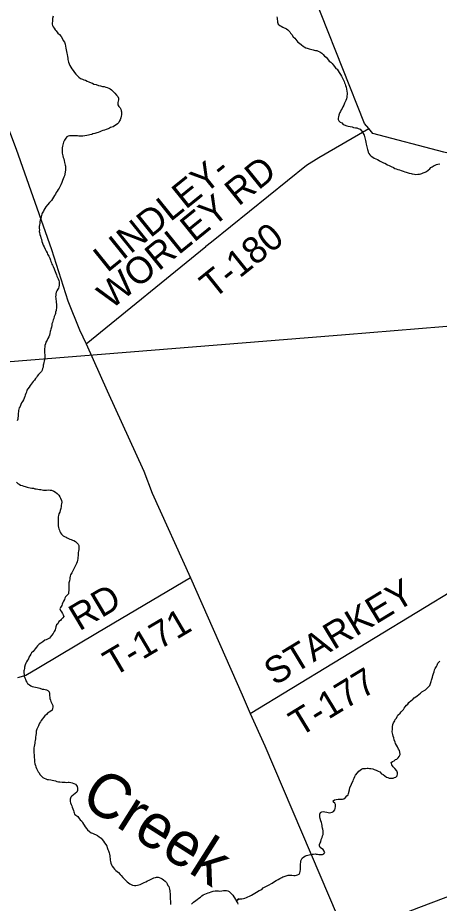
# Model space of a CAD drawing. Extents: x 0 to 1064, y 0 to 440.
# Drawn here: x 336.06 to 350.49, y 49.63 to 79.88 of the extents above; entities that cross this region are included whole.
import ezdxf

# ---------------------------------------------------------------- set-up
doc = ezdxf.new("R2010")
doc.units = 0
for name, color, linetype in [('GM_X_County_Road', 7, 'Continuous'), ('GM_X_Minor_River', 7, 'Continuous'), ('GM_X_Minor_River_Text', 7, 'Continuous'), ('GM_X_Rail_Line', 7, 'Continuous'), ('GM_X_State_Route', 7, 'Continuous'), ('GM_X_Township_Road', 7, 'Continuous'), ('GM_X_Township_Road_Text', 7, 'Continuous')]:
    doc.layers.add(name, color=color, linetype=linetype)

msp = doc.modelspace()

# ---------------------------------------------------------------- linework, layer by layer
at = {"layer": 'GM_X_County_Road'}
for points in [[(332.472, 81.833), (334.396, 78.519), (335.465, 76.831), (336.008, 75.395), (337.22, 71.966), (337.783, 70.207), (338.181, 69.223), (338.401, 68.74), (339.129, 67.136), (340.376, 64.388), (340.662, 63.636), (341.974, 60.741), (343.737, 56.745), (344.022, 56.108), (344.519, 55.001), (346.397, 50.602), (347.286, 48.52)], [(374.507, 71.33), (372.27, 72.9), (368.291, 75.769), (368.159, 75.856), (367.867, 75.885), (362.558, 75.761), (360.734, 75.905), (359.635, 76.08), (358.571, 76.181), (357.992, 76.105), (357.429, 75.907), (356.927, 75.727), (354.046, 75.188), (352.338, 74.965), (351.809, 75.028), (350.645, 75.289), (348.214, 75.929), (348.075, 76.096), (347.933, 76.267), (345.702, 81.875)]]:
    msp.add_lwpolyline(points, dxfattribs=at)
at = {"layer": 'GM_X_Minor_River'}
for points in [[(337.273, 79.934), (337.259, 79.849), (337.252, 79.807), (337.251, 79.752), (337.243, 79.71), (337.248, 79.661), (337.259, 79.618), (337.276, 79.569), (337.306, 79.52), (337.341, 79.47), (337.382, 79.427), (337.436, 79.358), (337.495, 79.302), (337.548, 79.234), (337.601, 79.154), (337.624, 79.105), (337.665, 79.043), (337.688, 78.975), (337.704, 78.914), (337.715, 78.841), (337.72, 78.786), (337.736, 78.731), (337.741, 78.67), (337.752, 78.627), (337.769, 78.554), (337.779, 78.493), (337.784, 78.45), (337.806, 78.365), (337.823, 78.309), (337.846, 78.248), (337.887, 78.186), (337.916, 78.131), (337.957, 78.075), (338.011, 78.013), (338.058, 77.957), (338.117, 77.889), (338.159, 77.851), (338.213, 77.808), (338.279, 77.782), (338.327, 77.762)], [(344.931, 79.914), (344.936, 79.865), (344.941, 79.822), (344.946, 79.773), (344.951, 79.731), (344.979, 79.657), (345.027, 79.613), (345.075, 79.588), (345.129, 79.562), (345.177, 79.537), (345.219, 79.524)], [(345.219, 79.524), (345.261, 79.498), (345.309, 79.461), (345.368, 79.398), (345.398, 79.355), (345.445, 79.305), (345.486, 79.231), (345.54, 79.181), (345.575, 79.138), (345.61, 79.095), (345.646, 79.045), (345.706, 79.007), (345.771, 78.951), (345.825, 78.913), (345.867, 78.882), (345.915, 78.856), (345.969, 78.837), (346.03, 78.817), (346.078, 78.804), (346.126, 78.796), (346.169, 78.783), (346.211, 78.77), (346.253, 78.763), (346.296, 78.756), (346.344, 78.736), (346.398, 78.711), (346.464, 78.673), (346.512, 78.629), (346.559, 78.567), (346.613, 78.529), (346.66, 78.48), (346.719, 78.399), (346.779, 78.361), (346.82, 78.312), (346.856, 78.268), (346.903, 78.218), (346.95, 78.15), (346.992, 78.119), (347.021, 78.07), (347.056, 78.008), (347.103, 77.94), (347.139, 77.884), (347.185, 77.798), (347.208, 77.749), (347.237, 77.7), (347.248, 77.657), (347.266, 77.608), (347.283, 77.565), (347.299, 77.503), (347.316, 77.442), (347.321, 77.375), (347.331, 77.302), (347.33, 77.26), (347.323, 77.217), (347.321, 77.162), (347.308, 77.108), (347.288, 77.048), (347.269, 77.006), (347.243, 76.958), (347.217, 76.897), (347.185, 76.837), (347.166, 76.777), (347.134, 76.729), (347.108, 76.681), (347.089, 76.639), (347.064, 76.591), (347.044, 76.549), (347.037, 76.494), (347.024, 76.452), (347.028, 76.403), (347.046, 76.36), (347.099, 76.317), (347.147, 76.285), (347.195, 76.235), (347.237, 76.216), (347.327, 76.183), (347.37, 76.176), (347.442, 76.162), (347.503, 76.149), (347.551, 76.135), (347.624, 76.121), (347.667, 76.114), (347.715, 76.101), (347.775, 76.069), (347.822, 76.019), (347.87, 75.964), (347.881, 75.921), (347.916, 75.865), (347.927, 75.822), (347.949, 75.731), (347.96, 75.682), (347.971, 75.627), (347.988, 75.566), (347.999, 75.517), (348.01, 75.468), (348.026, 75.382), (348.037, 75.339), (348.054, 75.29), (348.077, 75.247), (348.112, 75.192), (348.16, 75.148)], [(338.327, 77.762), (338.381, 77.743), (338.435, 77.711), (338.502, 77.691), (338.574, 77.653), (338.622, 77.64), (338.67, 77.614), (338.749, 77.594), (338.833, 77.562), (338.9, 77.548), (338.961, 77.534), (339.027, 77.526), (339.082, 77.507), (339.13, 77.494), (339.178, 77.474), (339.226, 77.449), (339.268, 77.417), (339.322, 77.373), (339.387, 77.299), (339.446, 77.237), (339.488, 77.187), (339.511, 77.132), (339.509, 77.077), (339.502, 77.029), (339.495, 76.986), (339.488, 76.944), (339.493, 76.901), (339.522, 76.846), (339.569, 76.796), (339.592, 76.753), (339.609, 76.704), (339.614, 76.661), (339.613, 76.612), (339.612, 76.564), (339.605, 76.515), (339.597, 76.461), (339.571, 76.395), (339.552, 76.352), (339.52, 76.299), (339.483, 76.257), (339.427, 76.216), (339.377, 76.186), (339.328, 76.157), (339.285, 76.146), (339.242, 76.129), (339.199, 76.112), (339.156, 76.088), (339.088, 76.066), (339.039, 76.043), (338.978, 76.026), (338.922, 76.009), (338.873, 75.986), (338.812, 75.963), (338.769, 75.952), (338.701, 75.929), (338.64, 75.912), (338.597, 75.895), (338.536, 75.878), (338.487, 75.867), (338.432, 75.857), (338.358, 75.84), (338.297, 75.835), (338.254, 75.83), (338.206, 75.832), (338.151, 75.839), (338.109, 75.84), (338.066, 75.841), (338.017, 75.848), (337.957, 75.85), (337.914, 75.845), (337.835, 75.841), (337.792, 75.835), (337.742, 75.806), (337.705, 75.765), (337.661, 75.699), (337.628, 75.627), (337.608, 75.542), (337.595, 75.494), (337.587, 75.439), (337.585, 75.36), (337.584, 75.299), (337.589, 75.257), (337.593, 75.202), (337.605, 75.159), (337.615, 75.11), (337.638, 75.055), (337.655, 75), (337.666, 74.933), (337.688, 74.847), (337.699, 74.804), (337.704, 74.755), (337.703, 74.713), (337.696, 74.67), (337.688, 74.61), (337.674, 74.531), (337.661, 74.477), (337.647, 74.434), (337.616, 74.38), (337.596, 74.314), (337.57, 74.248), (337.543, 74.175)], [(348.16, 75.148), (348.208, 75.116), (348.256, 75.085), (348.31, 75.059), (348.37, 75.033), (348.424, 75.002), (348.466, 74.976), (348.508, 74.957), (348.58, 74.925), (348.622, 74.906), (348.719, 74.855), (348.773, 74.829), (348.845, 74.797), (348.923, 74.759), (348.965, 74.733), (349.007, 74.72), (349.068, 74.7), (349.128, 74.681), (349.182, 74.661), (349.255, 74.635), (349.309, 74.616), (349.358, 74.602), (349.418, 74.583), (349.46, 74.575), (349.521, 74.556), (349.563, 74.549), (349.636, 74.535), (349.678, 74.528), (349.751, 74.532), (349.806, 74.537), (349.849, 74.548), (349.892, 74.559), (349.935, 74.576), (349.997, 74.605), (350.046, 74.628), (350.108, 74.675), (350.158, 74.723), (350.201, 74.758), (350.245, 74.788), (350.307, 74.829), (350.35, 74.846), (350.393, 74.863), (350.436, 74.88), (350.509, 74.891)], [(337.543, 74.175), (337.518, 74.121), (337.48, 74.055), (337.448, 74.014), (337.416, 73.96), (337.384, 73.906), (337.359, 73.858), (337.327, 73.804), (337.289, 73.75), (337.251, 73.696), (337.226, 73.636), (337.182, 73.607), (337.151, 73.565), (337.088, 73.487), (337.031, 73.422), (336.987, 73.362), (336.956, 73.308), (336.942, 73.266), (336.904, 73.206), (336.891, 73.164), (336.878, 73.121), (336.865, 73.073), (336.851, 73.025), (336.831, 72.971), (336.818, 72.904), (336.816, 72.855), (336.809, 72.807), (336.802, 72.746), (336.8, 72.685), (336.805, 72.637), (336.803, 72.582), (336.815, 72.539), (336.825, 72.478), (336.842, 72.423), (336.859, 72.356), (336.876, 72.313), (336.892, 72.239), (336.915, 72.184), (336.938, 72.111), (336.967, 72.049), (337.007, 71.969), (337.042, 71.901), (337.071, 71.846), (337.088, 71.797), (337.129, 71.729), (337.158, 71.661), (337.181, 71.6), (337.198, 71.551), (337.215, 71.508), (337.232, 71.465), (337.249, 71.422), (337.273, 71.379), (337.307, 71.305), (337.324, 71.262), (337.348, 71.213), (337.364, 71.158), (337.393, 71.096), (337.404, 71.054), (337.428, 71.01), (337.451, 70.961), (337.474, 70.906), (337.479, 70.857), (337.483, 70.802), (337.488, 70.748), (337.474, 70.687), (337.455, 70.645), (337.436, 70.603), (337.404, 70.549), (337.385, 70.501), (337.371, 70.446), (337.364, 70.398), (337.362, 70.349), (337.367, 70.294), (337.372, 70.252), (337.377, 70.209), (337.382, 70.16), (337.386, 70.081), (337.391, 70.02), (337.389, 69.96), (337.382, 69.917), (337.375, 69.875), (337.361, 69.82), (337.36, 69.778), (337.341, 69.736), (337.315, 69.669), (337.295, 69.609), (337.282, 69.561), (337.269, 69.519), (337.255, 69.47), (337.236, 69.422), (337.228, 69.368), (337.215, 69.307), (337.195, 69.241), (337.181, 69.198), (337.174, 69.156), (337.167, 69.089), (337.147, 69.035), (337.133, 68.981), (337.096, 68.927), (337.07, 68.861), (337.031, 68.795)], [(337.031, 68.795), (337.012, 68.74), (336.992, 68.686), (336.991, 68.631), (336.983, 68.577), (336.976, 68.528), (336.981, 68.474), (336.985, 68.419), (336.99, 68.376), (336.989, 68.303), (336.987, 68.242), (336.986, 68.2), (336.972, 68.145), (336.959, 68.097), (336.946, 68.049), (336.939, 68.006), (336.931, 67.946), (336.917, 67.891), (336.904, 67.843), (336.884, 67.789), (336.835, 67.748), (336.772, 67.688), (336.734, 67.634), (336.709, 67.592), (336.678, 67.551), (336.64, 67.503), (336.596, 67.449), (336.558, 67.402), (336.521, 67.36), (336.489, 67.318), (336.451, 67.258), (336.413, 67.204), (336.382, 67.156), (336.362, 67.09), (336.342, 67.042), (336.323, 66.988), (336.309, 66.939), (336.283, 66.879), (336.258, 66.825), (336.226, 66.771), (336.194, 66.723), (336.169, 66.669), (336.148, 66.597), (336.117, 66.555), (336.104, 66.513), (336.096, 66.464), (336.089, 66.416), (336.082, 66.367), (336.081, 66.319), (336.079, 66.27), (336.072, 66.215), (336.065, 66.167), (336.051, 66.106)], [(336.023, 64.016), (336.064, 63.972), (336.112, 63.94), (336.16, 63.915), (336.221, 63.895), (336.269, 63.876), (336.323, 63.862)], [(336.323, 63.862), (336.384, 63.843), (336.438, 63.829), (336.487, 63.822), (336.553, 63.808), (336.602, 63.807), (336.65, 63.788), (336.693, 63.781), (336.808, 63.766), (336.85, 63.758), (336.948, 63.744), (337.002, 63.743), (337.051, 63.741), (337.118, 63.746), (337.179, 63.738), (337.221, 63.737), (337.3, 63.705), (337.354, 63.673), (337.413, 63.629), (337.467, 63.573), (337.502, 63.518), (337.525, 63.469), (337.56, 63.389), (337.57, 63.328), (337.563, 63.279), (337.555, 63.225), (337.548, 63.182), (337.534, 63.11), (337.515, 63.049), (337.501, 62.989), (337.475, 62.929), (337.461, 62.874), (337.454, 62.826), (337.453, 62.777), (337.452, 62.723), (337.45, 62.662), (337.449, 62.613), (337.454, 62.564), (337.453, 62.522), (337.463, 62.461), (337.474, 62.418), (337.491, 62.369), (337.509, 62.326), (337.532, 62.283), (337.567, 62.239), (337.621, 62.183), (337.663, 62.158), (337.717, 62.132), (337.759, 62.113), (337.807, 62.094), (337.849, 62.068), (337.891, 62.055), (337.94, 62.036), (337.988, 62.016), (338.036, 61.985), (338.089, 61.941), (338.137, 61.891), (338.154, 61.848), (338.159, 61.793), (338.152, 61.751), (338.151, 61.709), (338.143, 61.66), (338.136, 61.612), (338.128, 61.557), (338.127, 61.496), (338.12, 61.454), (338.118, 61.399), (338.105, 61.345), (338.098, 61.296), (338.078, 61.236), (338.046, 61.17), (338.014, 61.116), (338.001, 61.074), (337.975, 61.026), (337.937, 60.966), (337.911, 60.912), (337.873, 60.846), (337.86, 60.803), (337.846, 60.749), (337.845, 60.707), (337.832, 60.646), (337.818, 60.573), (337.817, 60.525), (337.815, 60.464), (337.814, 60.415), (337.813, 60.367), (337.811, 60.318), (337.804, 60.258), (337.802, 60.203), (337.752, 60.149), (337.702, 60.096), (337.677, 60.048), (337.664, 60.006), (337.632, 59.946), (337.606, 59.898), (337.586, 59.843), (337.573, 59.801), (337.523, 59.735), (337.509, 59.681), (337.532, 59.632), (337.568, 59.582)], [(337.568, 59.582), (337.597, 59.527), (337.62, 59.484), (337.637, 59.429), (337.605, 59.375), (337.549, 59.327), (337.524, 59.285), (337.474, 59.25), (337.436, 59.178), (337.386, 59.137), (337.372, 59.07), (337.359, 59.01), (337.345, 58.967), (337.307, 58.908), (337.281, 58.841), (337.225, 58.776), (337.181, 58.728), (337.149, 58.68), (337.106, 58.657), (337.039, 58.628), (336.995, 58.611), (336.927, 58.564), (336.853, 58.517), (336.803, 58.476), (336.747, 58.423), (336.71, 58.375), (336.659, 58.321), (336.622, 58.274), (336.59, 58.232), (336.54, 58.184), (336.509, 58.142), (336.477, 58.082), (336.445, 58.035), (336.432, 57.98), (336.394, 57.932), (336.368, 57.878), (336.343, 57.83), (336.323, 57.77), (336.297, 57.698), (336.296, 57.649), (336.282, 57.607), (336.275, 57.564), (336.274, 57.516), (336.284, 57.437), (336.289, 57.388), (336.306, 57.333), (336.329, 57.283), (336.346, 57.222), (336.375, 57.179), (336.405, 57.136), (336.464, 57.086), (336.512, 57.054), (336.56, 57.035), (336.615, 57.027), (336.669, 57.014), (336.73, 57), (336.772, 56.987), (336.821, 56.974), (336.899, 56.947), (336.96, 56.94), (337.002, 56.933), (337.05, 56.919), (337.099, 56.894), (337.14, 56.85), (337.151, 56.789), (337.155, 56.716), (337.16, 56.668), (337.165, 56.625), (337.188, 56.57), (337.199, 56.521), (337.222, 56.471), (337.239, 56.428), (337.262, 56.379), (337.267, 56.324), (337.26, 56.276), (337.246, 56.228), (337.203, 56.186), (337.141, 56.157), (337.098, 56.128), (337.048, 56.08), (336.992, 56.033), (336.948, 55.979), (336.91, 55.926), (336.866, 55.872), (336.841, 55.83), (336.815, 55.782), (336.789, 55.728), (336.776, 55.686), (336.757, 55.638), (336.718, 55.572), (336.699, 55.505), (336.691, 55.438), (336.683, 55.36), (336.675, 55.311), (336.668, 55.244), (336.66, 55.184), (336.653, 55.141), (336.646, 55.093), (336.638, 55.045), (336.625, 54.984), (336.617, 54.936)], [(349.843, 56.8), (349.887, 56.847), (350.017, 56.923), (350.054, 56.965), (350.161, 57.072), (350.181, 57.138), (350.213, 57.204), (350.22, 57.247), (350.253, 57.349), (350.26, 57.41), (350.287, 57.482), (350.306, 57.536), (350.326, 57.597), (350.34, 57.651), (350.39, 57.717), (350.409, 57.759), (350.441, 57.825), (350.51, 57.896)], [(346.936, 52.997), (346.913, 53.052), (346.871, 53.077), (346.86, 53.126), (346.903, 53.162), (346.959, 53.178), (347.026, 53.183), (347.074, 53.182), (347.123, 53.181), (347.172, 53.185), (347.221, 53.196), (347.277, 53.238), (347.321, 53.297), (347.364, 53.327), (347.378, 53.381), (347.411, 53.502), (347.425, 53.587), (347.476, 53.665), (347.496, 53.725), (347.535, 53.815), (347.548, 53.857), (347.573, 53.899), (347.593, 53.954), (347.618, 54.008), (347.687, 54.079), (347.737, 54.139), (347.781, 54.174), (347.824, 54.209), (347.867, 54.227), (347.922, 54.231), (347.965, 54.236), (348.014, 54.241), (348.057, 54.24), (348.099, 54.233), (348.148, 54.232), (348.208, 54.218), (348.262, 54.199), (348.323, 54.173), (348.395, 54.141), (348.449, 54.115), (348.514, 54.053), (348.562, 54.021), (348.622, 53.983), (348.682, 53.933), (348.724, 53.92), (348.773, 53.907), (348.827, 53.9), (348.906, 53.898), (348.956, 53.921), (348.999, 53.938), (349.042, 53.986), (349.056, 54.046), (349.057, 54.089), (349.028, 54.15), (348.963, 54.237), (348.91, 54.287), (348.863, 54.355), (348.846, 54.398), (348.841, 54.44), (348.89, 54.476), (348.946, 54.499), (348.989, 54.534), (349.032, 54.551), (349.076, 54.599), (349.108, 54.647), (349.152, 54.713), (349.136, 54.786), (349.125, 54.847), (349.096, 54.89), (349.055, 54.976), (349.02, 55.026), (348.991, 55.081), (348.974, 55.136), (348.939, 55.216), (348.929, 55.277), (348.906, 55.339), (348.895, 55.388), (348.879, 55.479), (348.881, 55.57), (348.883, 55.655), (348.897, 55.734), (348.917, 55.794), (348.962, 55.86), (348.981, 55.902), (349.019, 55.95), (349.05, 56.01), (349.07, 56.052), (349.151, 56.117), (349.182, 56.171), (349.257, 56.248), (349.289, 56.296), (349.32, 56.338), (349.364, 56.392), (349.408, 56.433), (349.446, 56.481), (349.521, 56.552), (349.564, 56.575), (349.627, 56.647), (349.682, 56.676), (349.726, 56.717), (349.843, 56.8)], [(336.617, 54.936), (336.616, 54.881), (336.615, 54.826), (336.619, 54.771), (336.624, 54.704), (336.629, 54.656), (336.633, 54.601), (336.638, 54.546), (336.643, 54.503), (336.642, 54.455), (336.652, 54.388), (336.669, 54.338), (336.686, 54.289), (336.709, 54.234), (336.738, 54.167), (336.761, 54.123), (336.797, 54.08), (336.82, 54.031), (336.879, 53.969), (336.927, 53.919), (336.969, 53.9), (337.023, 53.874), (337.071, 53.855), (337.12, 53.853), (337.193, 53.846), (337.247, 53.838), (337.302, 53.825), (337.362, 53.811), (337.404, 53.792), (337.459, 53.772), (337.507, 53.771), (337.586, 53.763), (337.647, 53.762), (337.69, 53.761), (337.744, 53.759), (337.787, 53.764), (337.83, 53.763), (337.884, 53.75), (337.927, 53.743), (337.987, 53.723), (338.041, 53.697), (338.077, 53.654), (338.1, 53.611), (338.105, 53.562), (338.11, 53.519), (338.115, 53.477), (338.089, 53.423), (338.033, 53.375), (337.977, 53.328), (337.921, 53.287), (337.878, 53.257), (337.858, 53.185), (337.856, 53.106), (337.867, 53.063), (337.89, 53.002), (337.913, 52.959), (337.93, 52.91), (337.947, 52.854), (337.976, 52.799), (337.987, 52.756), (337.998, 52.713), (338.003, 52.671), (338.057, 52.633), (338.123, 52.589), (338.164, 52.527), (338.206, 52.483), (338.253, 52.428), (338.276, 52.384), (338.311, 52.335), (338.335, 52.292), (338.37, 52.242), (338.417, 52.186), (338.452, 52.131), (338.518, 52.075), (338.578, 52.037), (338.62, 52.024), (338.674, 51.998), (338.747, 51.966), (338.795, 51.94), (338.854, 51.896), (338.914, 51.846), (338.949, 51.803), (338.997, 51.753), (339.032, 51.691), (339.079, 51.635), (339.108, 51.574), (339.125, 51.531), (339.148, 51.47), (339.171, 51.42), (339.194, 51.347), (339.205, 51.304), (339.216, 51.249), (339.22, 51.2), (339.225, 51.158), (339.23, 51.097), (339.241, 51.054), (339.252, 50.999), (339.275, 50.938), (339.298, 50.894), (339.345, 50.833), (339.375, 50.789)], [(343.627, 49.775), (343.542, 49.71), (343.659, 49.78), (343.732, 49.778), (343.793, 49.789), (343.836, 49.806), (343.892, 49.823), (343.941, 49.846), (343.99, 49.869), (344.058, 49.904), (344.114, 49.939), (344.175, 49.974), (344.231, 50.009), (344.324, 50.068), (344.41, 50.102), (344.46, 50.15), (344.577, 50.208), (344.639, 50.249), (344.768, 50.319), (344.812, 50.348), (344.905, 50.407), (344.972, 50.435), (345.034, 50.47), (345.096, 50.505), (345.139, 50.535), (345.182, 50.546), (345.25, 50.569), (345.311, 50.585), (345.36, 50.59), (345.439, 50.588), (345.506, 50.581), (345.554, 50.58), (345.597, 50.585), (345.64, 50.596), (345.695, 50.625), (345.715, 50.673), (345.728, 50.715), (345.742, 50.776), (345.743, 50.836), (345.739, 50.897), (345.741, 50.976), (345.748, 51.025), (345.755, 51.079), (345.775, 51.121), (345.8, 51.163), (345.856, 51.211), (345.906, 51.246), (345.949, 51.263), (345.992, 51.274), (346.035, 51.285), (346.083, 51.296), (346.139, 51.307), (346.181, 51.306), (346.236, 51.311), (346.279, 51.31), (346.321, 51.303), (346.364, 51.296), (346.43, 51.288), (346.485, 51.293), (346.541, 51.316), (346.572, 51.358), (346.549, 51.413), (346.508, 51.462), (346.46, 51.494), (346.412, 51.538), (346.389, 51.587), (346.39, 51.636), (346.41, 51.69), (346.429, 51.732), (346.443, 51.811), (346.482, 51.877), (346.495, 51.931), (346.508, 51.979), (346.51, 52.052), (346.511, 52.101), (346.507, 52.156), (346.496, 52.198), (346.479, 52.248), (346.474, 52.29), (346.463, 52.339), (346.452, 52.388), (346.435, 52.449), (346.407, 52.529), (346.396, 52.578), (346.397, 52.62), (346.404, 52.669), (346.424, 52.723), (346.467, 52.752), (346.528, 52.763), (346.571, 52.756), (346.637, 52.742), (346.679, 52.729), (346.734, 52.722), (346.777, 52.727), (346.82, 52.738), (346.869, 52.761), (346.907, 52.821), (346.92, 52.869), (346.94, 52.93), (346.936, 52.997)], [(339.375, 50.789), (339.422, 50.746), (339.464, 50.714), (339.512, 50.677), (339.571, 50.614), (339.606, 50.571), (339.66, 50.503), (339.707, 50.459), (339.749, 50.421), (339.808, 50.359), (339.856, 50.322), (339.898, 50.296), (339.946, 50.271), (339.994, 50.245), (340.055, 50.238), (340.109, 50.23), (340.164, 50.241), (340.207, 50.252), (340.25, 50.27), (340.299, 50.287), (340.349, 50.31), (340.392, 50.339), (340.447, 50.362), (340.509, 50.391), (340.564, 50.414), (340.626, 50.449), (340.676, 50.478), (340.725, 50.495), (340.774, 50.512), (340.817, 50.517), (340.865, 50.516), (340.908, 50.503), (340.962, 50.483), (341.004, 50.464), (341.052, 50.433), (341.105, 50.383), (341.153, 50.339), (341.182, 50.296), (341.205, 50.24), (341.229, 50.197), (341.246, 50.154), (341.257, 50.112), (341.268, 50.057), (341.273, 50.008), (341.278, 49.965), (341.276, 49.91), (341.281, 49.862), (341.28, 49.819), (341.285, 49.758), (341.289, 49.709), (341.288, 49.637), (341.292, 49.582)], [(342.005, 49.595), (342.073, 49.66), (342.154, 49.719), (342.198, 49.754), (342.266, 49.801), (342.315, 49.831), (342.365, 49.878), (342.409, 49.914), (342.47, 49.942), (342.519, 49.959), (342.581, 49.988), (342.624, 50), (342.679, 50.023), (342.753, 50.045), (342.814, 50.05), (342.881, 50.048), (342.935, 50.047), (342.978, 50.046), (343.045, 50.05), (343.106, 50.061), (343.161, 50.066), (343.204, 50.065), (343.258, 50.057), (343.3, 50.032), (343.348, 49.988), (343.377, 49.945), (343.419, 49.907), (343.454, 49.852), (343.483, 49.809), (343.512, 49.753), (343.542, 49.71), (343.583, 49.648), (343.6, 49.593)]]:
    msp.add_lwpolyline(points, dxfattribs=at)
at = {"layer": 'GM_X_Rail_Line'}
msp.add_lwpolyline([(294.878, 64.688), (295.462, 64.818), (295.993, 64.914), (296.456, 64.984), (296.949, 65.05), (297.395, 65.101), (298.637, 65.203), (300.032, 65.313), (301.845, 65.455), (308.155, 65.944), (313.085, 66.333), (315.754, 66.545), (319.164, 66.817), (322.97, 67.113), (325.111, 67.285), (328.704, 67.57), (338.651, 68.362), (347.277, 69.057), (351.435, 69.397), (364.628, 70.454), (374.547, 71.26), (377.035, 71.469), (383.382, 71.976), (390.331, 72.542)], dxfattribs=at)
at = {"layer": 'GM_X_State_Route'}
msp.add_lwpolyline([(345.62, 47.878), (346.678, 48.282), (347.286, 48.52), (347.579, 48.634), (348.671, 49.054), (349.782, 49.485), (350.72, 49.841), (351.738, 50.233), (352.713, 50.607), (353.768, 51.027), (354.706, 51.39), (355.798, 51.81), (356.711, 52.161), (357.865, 52.603), (358.939, 53.005), (360.025, 53.43), (361.203, 53.878), (362.647, 54.446), (364.147, 55.024), (364.856, 55.302), (365.739, 55.642), (366.417, 55.891), (367.195, 56.191), (368.034, 56.502)], dxfattribs=at)
at = {"layer": 'GM_X_Township_Road'}
for points in [[(342.505, 72.072), (342.69, 72.222), (345.945, 74.839), (346.363, 75.1), (348.075, 76.096)], [(338.401, 68.74), (342.504, 72.07), (342.505, 72.072)], [(344.022, 56.108), (353.993, 62.171), (354.148, 62.333), (354.072, 62.577), (353.48, 63.625), (355.003, 64.501), (355.005, 64.503)], [(341.974, 60.741), (338.797, 58.87), (336.782, 57.667), (336.346, 57.413), (336.053, 57.332)]]:
    msp.add_lwpolyline(points, dxfattribs=at)

# ---------------------------------------------------------------- texts
at = {"layer": 'GM_X_Minor_River_Text'}
msp.add_text('Creek', height=1.5151, rotation=327.6852, dxfattribs=at).set_placement((338.149, 53.052))
at = {"layer": 'GM_X_Township_Road_Text'}
for s, rotation, p in [('WORLEY RD', 38.9869, (339.26, 69.891)), ('LINDLEY-', 38.8434, (339.128, 71.152)), ('T-180', 38.8347, (342.763, 70.244)), ('STARKEY', 31.2452, (344.851, 57.043)), ('RD', 30.7917, (338.173, 58.911)), ('T-171', 30.5794, (339.345, 57.352)), ('T-177', 31.3494, (345.71, 55.296))]:
    msp.add_text(s, height=0.9091, rotation=rotation, dxfattribs=at).set_placement(p)

doc.saveas('drawing.dxf')
